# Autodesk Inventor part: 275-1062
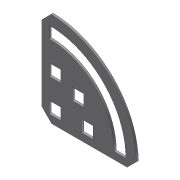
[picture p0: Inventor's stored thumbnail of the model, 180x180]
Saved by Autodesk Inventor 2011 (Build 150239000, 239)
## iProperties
Company: Autodesk Inc.
Created: 2005-07
Part Number: 275-1062
Document SubType Name: Modeling
Designer: Autodesk Inc.
Density: 1 g/cm^3
Catalog Web Link: http://www.vexrobotics.com/products/accessories/structure/275-1062.html
Description: Bracket allows parts to be connected at any angle from 0 to 90 degrees. Can also be used as a corner gusset.
Vendor: Innovation First, Inc.
Title: VEX Robotics Kit of Parts
Author: Autodesk Inc.
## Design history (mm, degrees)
sketch "Sketch1"
  geometry: L1 (-25.458, -1.634)-(-20.886, -1.634); L2 (-20.886, -1.634)-(-20.886, -6.206); L3 (-20.886, -6.206)-(-25.458, -6.206); L4 (-25.458, -6.206)-(-25.458, -1.634); L5 (-12.758, -6.206)-(-8.186, -6.206); L6 (-8.186, -6.206)-(-8.186, -1.634); L7 (-8.186, -1.634)-(-12.758, -1.634); L8 (-12.758, -1.634)-(-12.758, -6.206); L9 (-0.058, -6.206)-(4.514, -6.206); L10 (-25.458, 6.494)-(-20.886, 6.494); L11 (-20.886, 6.494)-(-20.886, 11.066); L12 (-20.886, 11.066)-(-25.458, 11.066); L13 (-25.458, 11.066)-(-25.458, 6.494); L14 (-25.458, 23.766)-(-25.458, 19.194); L15 (-24.442, -9)-(5.022, -9); L16 (-28.252, -5.19)-(-28.252, 24.274); L17 (-28.252, -5.19)-(-24.442, -9); L18 (-24.442, -9)-(-28.252, -5.19); L19 (-28.252, 24.274)-(-24.705, 27.822); L20 (8.569, -5.452)-(5.022, -9); L21 (-16.441, 2.811)-(-11.869, 2.811); L22 (-11.869, 2.811)-(-11.869, 7.383); L23 (-11.869, 7.383)-(-16.441, 7.383); L24 (-16.441, 7.383)-(-16.441, 2.811); A1 r 25.4 centre (-25.458, -6.206) between (-0.058, -6.206) and (-25.458, 19.194); A2 r 29.972 centre (-25.458, -6.206) between (4.514, -6.206) and (-25.458, 23.766); A3 r 34.036 centre (-25.458, -6.206) between (8.569, -5.452) and (-24.705, 27.822); 2 further points
  constraints: 48 end point, 8 parallel, 6 perpendicular, 6 point on circle, 6 point on line, 5 collinear, 5 horizontal, 3 centre point, 3 coincident
  dimensions: "d0" = 4.572 distance of L2.end L3.end; "d1" = 4.572 distance of L1.end L2.end; "d2" = 4.572 distance of L5.start L5.end; "d3" = 4.572 distance of L9.start L9.end; "d4" = 4.572 distance of L12.end L10.start; "d5" = 4.572 distance of L14.start L14.end; "d6" = 8.128 distance between parallel lines of L10 L1; "d8" = 8.128 distance between parallel lines of L8 L2; "d10" = 4.064 radial gap between concentric circles of A3 A2; "d11" = 2.794 distance between parallel lines of L15 L3; "d12" = 2.794 distance between parallel lines of L16 L4; "d13" = 3.81 distance of L17.start point (-28.252, -9); "d14" = 3.81 distance of L17.end point (-28.252, -9) (= d13); "d15" = 3.81 distance of L15.start point (-28.252, -9) (= d13); "d16" = 3.81 distance of L16.start point (-28.252, -9) (= d15); "d18" = 45 deg angle of L16 L19; "d22" = 4.572 distance of L21.start L21.end; "d23" = 4.445 distance between parallel lines of L7 L21; "d24" = 4.445 distance between parallel lines of L24 L11; "d25" = 4.572 distance between parallel lines of L23 L21
extrude "Extrusion1" new body sketch "Sketch1" distance "d26" = 0.8382; taper "d27" = 0 deg
body "Solid1"
